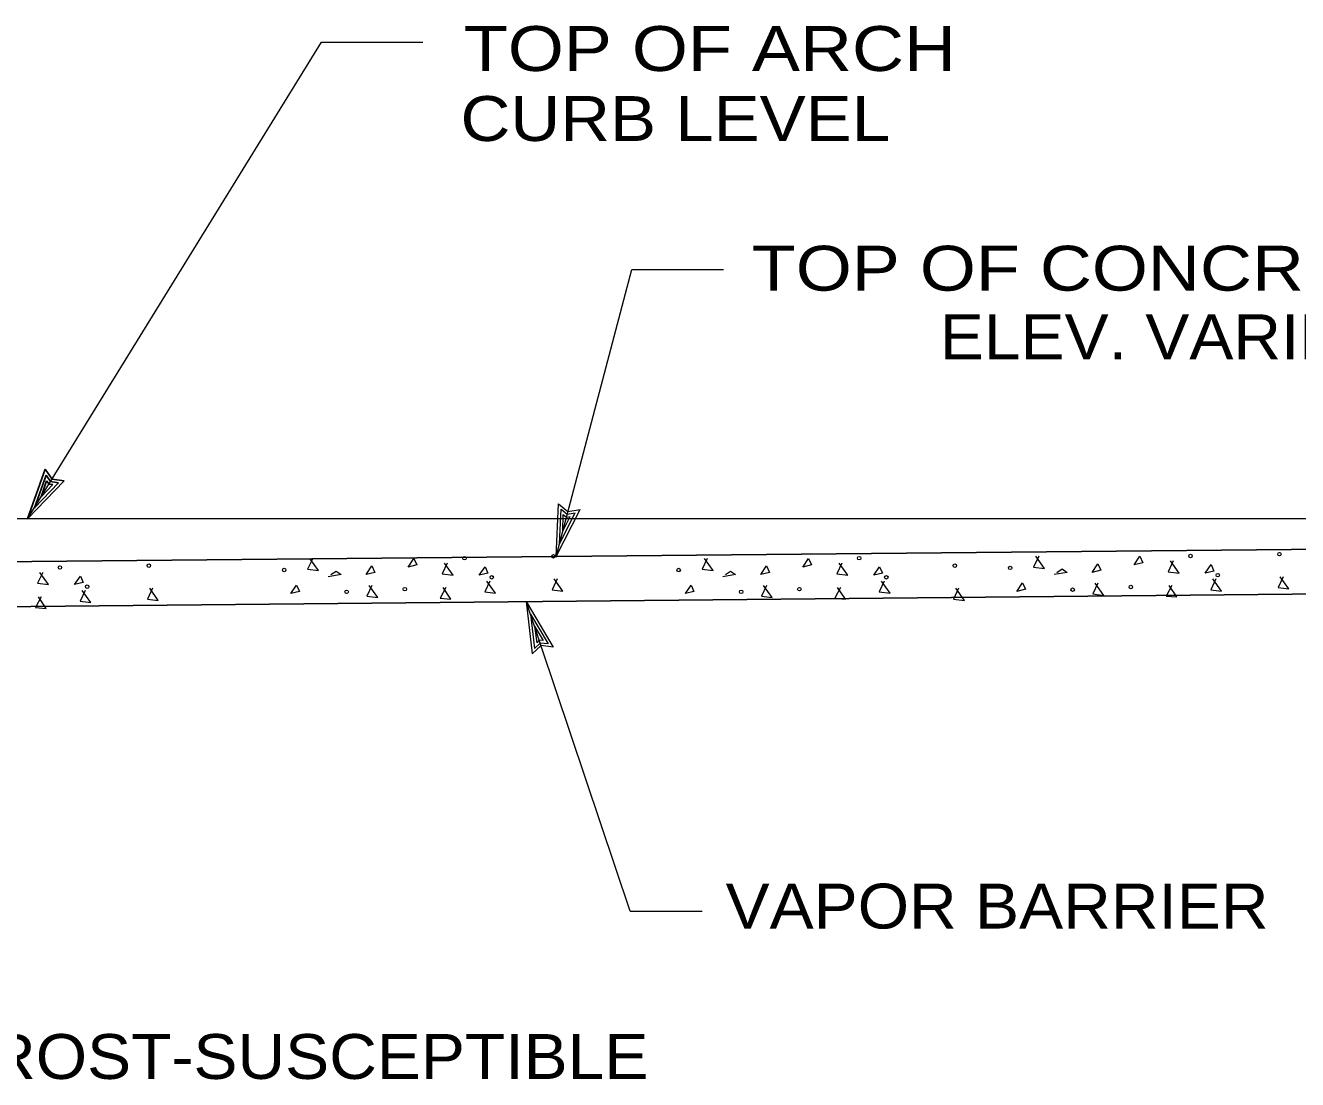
# Model space of a CAD drawing. Extents: x -22.3 to 19.7, y -11.8 to 18.2.
# Drawn here: x -16.262 to -12.719, y -9.094 to -6.158 of the extents above; entities that cross this region are included whole.
import ezdxf
from ezdxf.enums import TextEntityAlignment as Align

# ---------------------------------------------------------------- set-up
doc = ezdxf.new("R2010")
doc.units = 0
doc.header["$LTSCALE"] = 0.05
doc.layers.add('1', color=7, linetype='Continuous', lineweight=13)
doc.layers.add('2', color=7, linetype='Continuous', lineweight=13)

msp = doc.modelspace()

# ---------------------------------------------------------------- linework, layer by layer
at = {"layer": '1'}
for p, q in [((-16.25642, -7.53269), (-16.20742, -7.39369)), ((-16.25642, -7.53269), (-16.15442, -7.42669)), ((-16.23742, -7.50169), (-16.20442, -7.41069)), ((-16.23742, -7.50169), (-16.17042, -7.43169)), ((-16.21842, -7.47069), (-16.20342, -7.42669)), ((-16.21842, -7.47069), (-16.18642, -7.43669)), ((-16.20442, -7.41069), (-16.19242, -7.42869)), ((-16.20342, -7.42669), (-16.19642, -7.43569)), ((-16.19642, -7.43569), (-16.18642, -7.43669)), ((-16.19242, -7.42869), (-16.17042, -7.43169)), ((-14.78442, -7.63769), (-14.77742, -7.49069)), ((-14.78442, -7.63769), (-14.71742, -7.50669)), ((-14.77542, -7.60169), (-14.77042, -7.50569)), ((-14.77042, -7.50569), (-14.75342, -7.51969)), ((-5.69442, -7.53269), (-18.28242, -7.53269)), ((-14.77542, -7.60169), (-14.73142, -7.51569)), ((-14.76542, -7.56669), (-14.76442, -7.52069)), ((-14.76542, -7.56669), (-14.74542, -7.52569)), ((-14.76442, -7.52069), (-14.75542, -7.52769)), ((-14.75542, -7.52769), (-14.74542, -7.52569)), ((-14.75342, -7.51969), (-14.73142, -7.51569)), ((-14.57842, -8.62569), (-14.86742, -7.76269)), ((-14.86742, -7.76269), (-14.79242, -7.88969)), ((-14.86742, -7.76269), (-14.85142, -7.90869)), ((-14.85542, -7.79769), (-14.80642, -7.88069)), ((-14.85542, -7.79769), (-14.84442, -7.89369)), ((-14.84442, -7.83169), (-14.83842, -7.87769)), ((-14.84442, -7.83169), (-14.82042, -7.87169)), ((-14.82842, -7.87869), (-14.84442, -7.89369)), ((-14.83142, -7.87069), (-14.83842, -7.87769)), ((-14.82042, -7.87169), (-14.83142, -7.87069)), ((-14.80642, -7.88069), (-14.82842, -7.87869)), ((-14.57842, -8.62569), (-14.37742, -8.62569))]:
    msp.add_line(p, q, dxfattribs=at)
at = {"layer": '1', "lineweight": 25}
for p, q in [((-16.25642, -7.53269), (-16.20742, -7.39369)), ((-16.25642, -7.53269), (-16.15442, -7.42669)), ((-16.23742, -7.50169), (-16.20442, -7.41069)), ((-16.23742, -7.50169), (-16.17042, -7.43169)), ((-16.21842, -7.47069), (-16.20342, -7.42669)), ((-16.21842, -7.47069), (-16.18642, -7.43669)), ((-16.20442, -7.41069), (-16.19242, -7.42869)), ((-16.20342, -7.42669), (-16.19642, -7.43569)), ((-16.19642, -7.43569), (-16.18642, -7.43669)), ((-16.19242, -7.42869), (-16.17042, -7.43169)), ((-16.90342, -7.65769), (-11.00642, -7.60069)), ((-16.90242, -7.78269), (-11.01242, -7.72569))]:
    msp.add_line(p, q, dxfattribs=at)
at = {"layer": '1'}
for points in [[(-16.25642, -7.53269), (-15.43742, -6.20469), (-15.15542, -6.20469)], [(-14.78442, -7.63769), (-14.57342, -6.83769), (-14.31842, -6.83769)], [(-16.20742, -7.39369), (-16.18842, -7.42169), (-16.15442, -7.42669)], [(-14.77742, -7.49069), (-14.75142, -7.51169), (-14.71742, -7.50669)], [(-14.79242, -7.88969), (-14.82642, -7.88569), (-14.85142, -7.90869)]]:
    msp.add_lwpolyline(points, dxfattribs=at)
at = {"layer": '1', "lineweight": 25}
msp.add_lwpolyline([(-16.20742, -7.39369), (-16.18842, -7.42169), (-16.15442, -7.42669)], dxfattribs=at)
at = {"layer": '2'}
for points in [[(-15.46242, -7.64269), (-15.47642, -7.67269), (-15.44642, -7.67669), (-15.47042, -7.64269)], [(-14.36342, -7.64269), (-14.37742, -7.67269), (-14.34742, -7.67669), (-14.37142, -7.64269)], [(-13.44042, -7.63669), (-13.45442, -7.66669), (-13.42442, -7.67069), (-13.44842, -7.63669)], [(-13.06542, -7.64969), (-13.07942, -7.67969), (-13.04942, -7.68369), (-13.07342, -7.64969)], [(-16.21442, -7.68169), (-16.22842, -7.71169), (-16.19842, -7.71569), (-16.22242, -7.68169)], [(-15.41142, -7.68769), (-15.39742, -7.67769), (-15.38342, -7.68769), (-15.41942, -7.69369)], [(-15.08742, -7.65569), (-15.10142, -7.68569), (-15.07142, -7.68969), (-15.09542, -7.65569)], [(-14.31242, -7.68769), (-14.29842, -7.67769), (-14.28442, -7.68769), (-14.32042, -7.69369)], [(-13.98842, -7.65569), (-14.00242, -7.68569), (-13.97242, -7.68969), (-13.99642, -7.65569)], [(-13.38942, -7.68169), (-13.37542, -7.67169), (-13.36142, -7.68169), (-13.39742, -7.68769)], [(-15.29742, -7.71769), (-15.31142, -7.74769), (-15.28142, -7.75169), (-15.30542, -7.71769)], [(-15.09142, -7.72369), (-15.10742, -7.75369), (-15.07742, -7.75569), (-15.09942, -7.72369)], [(-14.96942, -7.70569), (-14.98342, -7.73569), (-14.95342, -7.73969), (-14.97742, -7.70569)], [(-14.78142, -7.69969), (-14.79542, -7.72969), (-14.76542, -7.73369), (-14.78942, -7.69969)], [(-14.19842, -7.71769), (-14.21242, -7.74769), (-14.18242, -7.75169), (-14.20642, -7.71769)], [(-13.99242, -7.72369), (-14.00842, -7.75369), (-13.97842, -7.75569), (-14.00042, -7.72369)], [(-13.87042, -7.70569), (-13.88442, -7.73569), (-13.85442, -7.73969), (-13.87842, -7.70569)], [(-13.27542, -7.71169), (-13.28942, -7.74169), (-13.25942, -7.74569), (-13.28342, -7.71169)], [(-13.06942, -7.71769), (-13.08542, -7.74769), (-13.05542, -7.74969), (-13.07742, -7.71769)], [(-12.94742, -7.69969), (-12.96142, -7.72969), (-12.93142, -7.73369), (-12.95542, -7.69969)], [(-12.75942, -7.69369), (-12.77342, -7.72369), (-12.74342, -7.72769), (-12.76742, -7.69369)], [(-16.21842, -7.74969), (-16.23442, -7.77969), (-16.20442, -7.78169), (-16.22642, -7.74969)], [(-16.09642, -7.73169), (-16.11042, -7.76169), (-16.08042, -7.76569), (-16.10442, -7.73169)], [(-15.90842, -7.72569), (-15.92242, -7.75569), (-15.89242, -7.75969), (-15.91642, -7.72569)], [(-13.66342, -7.72569), (-13.67742, -7.75569), (-13.64742, -7.75969), (-13.67142, -7.72569)]]:
    msp.add_lwpolyline(points, dxfattribs=at)
for points in [[(-15.19642, -7.66669), (-15.18042, -7.64269), (-15.17242, -7.66069)], [(-14.09742, -7.66669), (-14.08142, -7.64269), (-14.07342, -7.66069)], [(-13.17442, -7.66069), (-13.15842, -7.63669), (-13.15042, -7.65469)], [(-15.31342, -7.68769), (-15.29742, -7.66369), (-15.28942, -7.68169)], [(-14.99842, -7.68969), (-14.98242, -7.66569), (-14.97442, -7.68369)], [(-14.21442, -7.68769), (-14.19842, -7.66369), (-14.19042, -7.68169)], [(-13.89942, -7.68969), (-13.88342, -7.66569), (-13.87542, -7.68369)], [(-13.29142, -7.68169), (-13.27542, -7.65769), (-13.26742, -7.67569)], [(-12.97642, -7.68369), (-12.96042, -7.65969), (-12.95242, -7.67769)], [(-16.12542, -7.71569), (-16.10942, -7.69169), (-16.10142, -7.70969)], [(-15.52342, -7.74069), (-15.50742, -7.71669), (-15.49942, -7.73469)], [(-14.42442, -7.74069), (-14.40842, -7.71669), (-14.40042, -7.73469)], [(-13.50142, -7.73469), (-13.48542, -7.71069), (-13.47742, -7.72869)]]:
    msp.add_lwpolyline(points, close=True, dxfattribs=at)
for centre in [(-15.03942, -7.64206), (-14.79192, -7.63681), (-13.94042, -7.64206), (-13.01742, -7.63606), (-12.76992, -7.63081), (-16.16642, -7.66806), (-15.91892, -7.66281), (-15.54192, -7.67506), (-14.44292, -7.67506), (-13.67392, -7.66281), (-13.51992, -7.66906), (-12.94167, -7.68931), (-16.09067, -7.72131), (-15.20592, -7.72831), (-14.96367, -7.69531), (-14.10692, -7.72831), (-13.86467, -7.69531), (-13.18392, -7.72231), (-15.36792, -7.73581), (-14.26892, -7.73581), (-13.34592, -7.72981)]:
    msp.add_circle(centre, 0.00487, dxfattribs=at)

# ---------------------------------------------------------------- texts
at = {"layer": '1'}
for s, width, p in [('TOP OF ARCH', 1.2, (-15.04142, -6.28469)), ('TOP OF CONCRETE SLAB', 1.2, (-14.23942, -6.89669)), ('VAPOR BARRIER', 1.1, (-14.31242, -8.67369)), ('NONFROST-SUSCEPTIBLE', 1.1, (-16.88742, -9.09269))]:
    msp.add_text(s, height=0.125, dxfattribs=dict(at, width=width)).set_placement(p)
for s, width, p in [('CURB LEVEL', 1.15, (-14.45242, -6.47969)), ('ELEV. VARIES', 1.1, (-13.09242, -7.08769))]:
    msp.add_text(s, height=0.125, dxfattribs=dict(at, width=width)).set_placement(p, align=Align.CENTER)

doc.saveas('drawing.dxf')
